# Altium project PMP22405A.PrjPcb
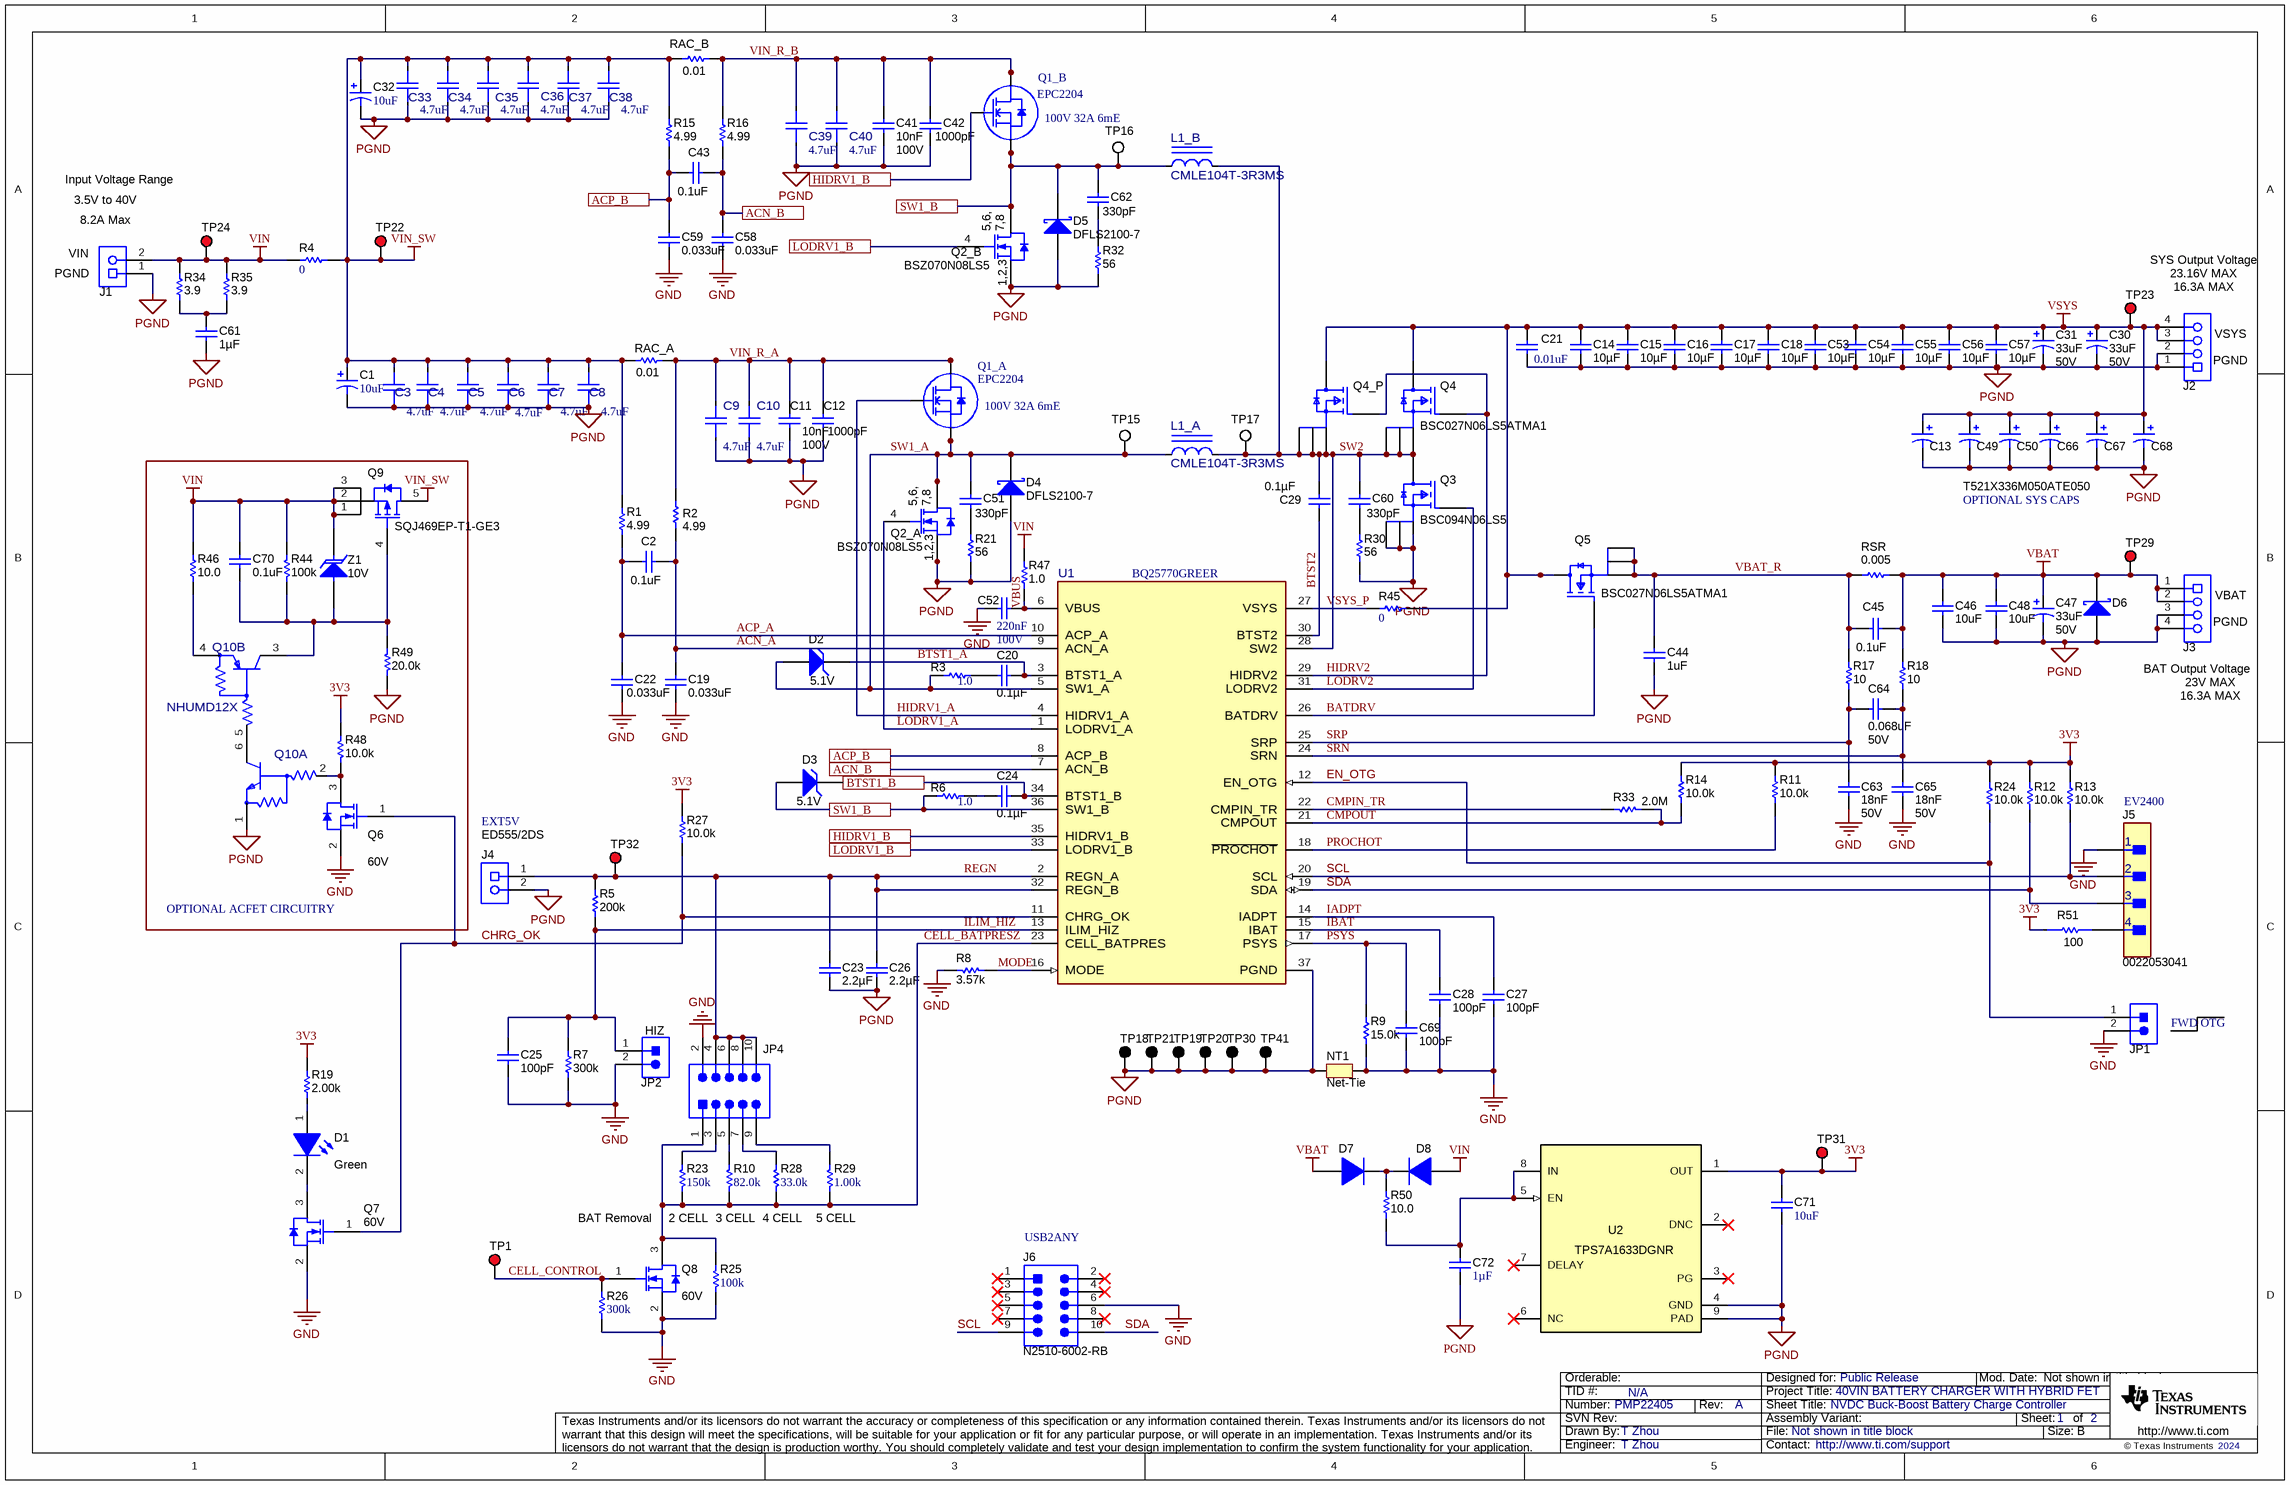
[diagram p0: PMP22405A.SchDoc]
TID: N/A; TechSupport: http://www.ti.com/support; SCH_Rev: A; PRJ_Title: 40VIN BATTERY CHARGER WITH HYBRID FET; PRJ_Number: PMP22405; PRJ_Engineer: T Zhou; PRJ_Customer: Public Release; PCB_Rev: A; PCB_Layout: T Zhou; CopyrightYear: 2024
2 sheets, 197 parts. Net scope: global (net labels, ports and power ports of the same name join across sheets).
Board file: PMP22405A.PcbDoc
Sheets:
  PMP22405A.SchDoc
  PMP22405A_Hardware.SchDoc

## Sheet PMP22405A.SchDoc: NVDC Buck-Boost Battery Charge Controller
size 431 x 279 mm; Date: Not shown in title block; ApprovedBy: Not shown in title block; CheckedBy: Not shown in title block; Author: Not shown in title block; CompanyName: Not shown in title block; DrawnBy: T Zhou; Engineer: Not shown in title block; Organization: Not shown in title block; Address1: Not shown in title block; Address2: Not shown in title block; Address3: Not shown in title block; Address4: Not shown in title block; DocumentNumber: 1; Revision: Use project parameter SCH_Rev; SheetNumber: 1; SheetTotal: 2; PageSetup: Record=PageOptions¦CenterHorizontal=True¦CenterVertical=True¦PrintScale=1.00¦XCorrection=1.00¦YCorrection=1.00¦PrintKind=0¦BorderSize=5000000¦LeftOffset=0¦BottomOffset=0¦Orientation=2¦PaperLength=1000¦PaperWidth=1000¦Scale=100¦PaperSource=15¦PrintQuality=600¦MediaType=1¦DitherType=10¦PaperKind=Letter¦PrintScaleMode=1

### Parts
C1  ValueDisplayed: 10uF  [7343-43]  (hidden comment: TR3E106K063C0600)
C2  ValueDisplayed: 0.1uF  [0603S]  (hidden comment: CGA3E2X7R1H104K080AA)
C3  ValueDisplayed: 4.7uF  [FP-C2012X5R2A475K125AC_0805-MFG]  (hidden comment: C2012X5R2A475K125AC)
C4  ValueDisplayed: 4.7uF  [FP-C2012X5R2A475K125AC_0805-MFG]  (hidden comment: C2012X5R2A475K125AC)
C5  ValueDisplayed: 4.7uF  [FP-C2012X5R2A475K125AC_0805-MFG]  (hidden comment: C2012X5R2A475K125AC)
C6  ValueDisplayed: 4.7uF  [FP-C2012X5R2A475K125AC_0805-MFG]  (hidden comment: C2012X5R2A475K125AC)
C7  ValueDisplayed: 4.7uF  [FP-C2012X5R2A475K125AC_0805-MFG]  (hidden comment: C2012X5R2A475K125AC)
C8  ValueDisplayed: 4.7uF  [FP-C2012X5R2A475K125AC_0805-MFG]  (hidden comment: C2012X5R2A475K125AC)
C9  ValueDisplayed: 4.7uF  [FP-C2012X5R2A475K125AC_0805-MFG]  (hidden comment: C2012X5R2A475K125AC)
C10  ValueDisplayed: 4.7uF  [FP-C2012X5R2A475K125AC_0805-MFG]  (hidden comment: C2012X5R2A475K125AC)
C11  Cap_F: 10nF  VDC_V: 100V  [0603S]  (hidden comment: C0603C103J1RACTU)
C12  ValueDisplayed: 1000pF  [0402S]  (hidden comment: GRM155R72A102KA01D)
C13  T521X336M050ATE050  [7343-43]  (value not drawn)
C14  ValueDisplayed: 10µF  [0805_HV]  (hidden comment: C2012JB1V106K125AC)
C15  ValueDisplayed: 10µF  [0805_HV]  (hidden comment: C2012JB1V106K125AC)
C16  ValueDisplayed: 10µF  [0805_HV]  (hidden comment: C2012JB1V106K125AC)
C17  ValueDisplayed: 10µF  [0805_HV]  (hidden comment: C2012JB1V106K125AC)
C18  ValueDisplayed: 10µF  [0805_HV]  (hidden comment: C2012JB1V106K125AC)
C19  ValueDisplayed: 0.033uF  [0603S]  (hidden comment: CGA3E3X7S2A333K080AB)
C20  ValueDisplayed: 0.1µF  [0402S]  (hidden comment: CGA2B3X7R1E104K050BB)
C21  ValueDisplayed: 0.01uF  [0603S]  (hidden comment: C0603C103J1RACTU)
C22  ValueDisplayed: 0.033uF  [0603S]  (hidden comment: CGA3E3X7S2A333K080AB)
C23  ValueDisplayed: 2.2µF  [0402S]  (hidden comment: GRM155R61E225ME15D)
C24  ValueDisplayed: 0.1µF  [0402S]  (hidden comment: CGA2B3X7R1E104K050BB)
C25  ValueDisplayed: 100pF  [0402S]  (hidden comment: GRM1555C1H101JA01D)
C26  ValueDisplayed: 2.2µF  [0402S]  (hidden comment: GRM155R61E225ME15D)
C27  ValueDisplayed: 100pF  [0402S]  (hidden comment: GRM1555C1H101JA01D)
C28  ValueDisplayed: 100pF  [0402S]  (hidden comment: GRM1555C1H101JA01D)
C29  ValueDisplayed: 0.1µF  [0402S]  (hidden comment: CGA2B3X7R1E104K050BB)
C30  ValueDisplayed: 33uF  VDC_V: 50V  [7343-43]  (hidden comment: T521X336M050ATE050)
C31  ValueDisplayed: 33uF  VDC_V: 50V  [7343-43]  (hidden comment: T521X336M050ATE050)
C32  ValueDisplayed: 10uF  [7343-43]  (hidden comment: TR3E106K063C0600)
C33  ValueDisplayed: 4.7uF  [FP-C2012X5R2A475K125AC_0805-MFG]  (hidden comment: C2012X5R2A475K125AC)
C34  ValueDisplayed: 4.7uF  [FP-C2012X5R2A475K125AC_0805-MFG]  (hidden comment: C2012X5R2A475K125AC)
C35  ValueDisplayed: 4.7uF  [FP-C2012X5R2A475K125AC_0805-MFG]  (hidden comment: C2012X5R2A475K125AC)
C36  ValueDisplayed: 4.7uF  [FP-C2012X5R2A475K125AC_0805-MFG]  (hidden comment: C2012X5R2A475K125AC)
C37  ValueDisplayed: 4.7uF  [FP-C2012X5R2A475K125AC_0805-MFG]  (hidden comment: C2012X5R2A475K125AC)
C38  ValueDisplayed: 4.7uF  [FP-C2012X5R2A475K125AC_0805-MFG]  (hidden comment: C2012X5R2A475K125AC)
C39  ValueDisplayed: 4.7uF  [FP-C2012X5R2A475K125AC_0805-MFG]  (hidden comment: C2012X5R2A475K125AC)
C40  ValueDisplayed: 4.7uF  [FP-C2012X5R2A475K125AC_0805-MFG]  (hidden comment: C2012X5R2A475K125AC)
C41  Cap_F: 10nF  VDC_V: 100V  [0603S]  (hidden comment: C0603C103J1RACTU)
C42  ValueDisplayed: 1000pF  [0402S]  (hidden comment: GRM155R72A102KA01D)
C43  ValueDisplayed: 0.1uF  [0603S]  (hidden comment: CGA3E2X7R1H104K080AA)
C44  ValueDisplayed: 1uF  [0603S]  (hidden comment: C1608X5R1H105K080AB)
C45  ValueDisplayed: 0.1uF  [0603S]  (hidden comment: CGA3E2X7R1H104K080AA)
C46  ValueDisplayed: 10uF  [1206_180]  (hidden comment: C3216X7R1V106K160AC)
C47  ValueDisplayed: 33uF  VDC_V: 50V  [7343-43]  (hidden comment: T521X336M050ATE050)
C48  ValueDisplayed: 10uF  [1206_180]  (hidden comment: C3216X7R1V106K160AC)
C49  T521X336M050ATE050  [7343-43]  (value not drawn)
C50  T521X336M050ATE050  [7343-43]  (value not drawn)
C51  ValueDisplayed: 330pF  [0603S]  (hidden comment: Capacitor)
C52  Cap_F: 220nF  VDC_V: 100V  [0603S]  (hidden comment: HMK107C7224MAHTE)
C53  ValueDisplayed: 10µF  [0805_HV]  (hidden comment: C2012JB1V106K125AC)
C54  ValueDisplayed: 10µF  [0805_HV]  (hidden comment: C2012JB1V106K125AC)
C55  ValueDisplayed: 10µF  [0805_HV]  (hidden comment: C2012JB1V106K125AC)
C56  ValueDisplayed: 10µF  [0805_HV]  (hidden comment: C2012JB1V106K125AC)
C57  ValueDisplayed: 10µF  [0805_HV]  (hidden comment: C2012JB1V106K125AC)
C58  ValueDisplayed: 0.033uF  [0603S]  (hidden comment: CGA3E3X7S2A333K080AB)
C59  ValueDisplayed: 0.033uF  [0603S]  (hidden comment: CGA3E3X7S2A333K080AB)
C60  ValueDisplayed: 330pF  [0603S]  (hidden comment: Capacitor)
C61  ValueDisplayed: 1µF  [0805_HV]  (hidden comment: C2012X7S2A105K125AE)
C62  ValueDisplayed: 330pF  [0603S]  (hidden comment: Capacitor)
C63  Cap_F: 18nF  VDC_V: 50V  [0402S]  (hidden comment: GRM155R71H183KA12D)
C64  ValueDisplayed: 0.068uF  VDC_V: 50V  [0402S]  (hidden comment: CGA2B3X7R1H683K050BB)
C65  Cap_F: 18nF  VDC_V: 50V  [0402S]  (hidden comment: GRM155R71H183KA12D)
C66  T521X336M050ATE050  [7343-43]
C67  T521X336M050ATE050  [7343-43]  (value not drawn)
C68  T521X336M050ATE050  [7343-43]  (value not drawn)
C69  ValueDisplayed: 100pF  [0402S]  (hidden comment: GRM1555C1H101JA01D)
C70  ValueDisplayed: 0.1uF  [0603S]  (hidden comment: CGA3E2X7R1H104K080AA)
C71  ValueDisplayed: 10uF  [0603S]  (hidden comment: GRM188R6YA106MA73D)
C72  ValueDisplayed: 1µF  [0805_HV]  (hidden comment: C2012X7S2A105K125AE)
D1  value Green  [LED_LTST-C190]  (hidden comment: LED)
D2  value 5.1V  [SOD-323F]  (hidden comment: D3Z5V1BF-7)
D3  value 5.1V  [SOD-323F]  (hidden comment: D3Z5V1BF-7)
D4  DFLS2100-7  [PowerDI123]
D5  DFLS2100-7  [PowerDI123]
D6  B240A-13-F  [SMA]  (value not drawn)
D7  1N4148WQ-7-F  [SOD-123]  (value not drawn)
D8  1N4148WQ-7-F  [SOD-123]  (value not drawn)
J1  Receptacle_2x1  [On-Shore_ED120_2DS]  (value not drawn)
J2  ED120/4DS  [On-Shore_ED120_4DS]  (value not drawn)
J3  ED120/4DS  [On-Shore_ED120_4DS]  (value not drawn)
J4  ED555/2DS  [TERM_BLK_ED555-2DS]
J5  0022053041  [FP-22-05-3041_HDR4-MFG]
J6  N2510-6002-RB  [CONN_2510-6002]
JP1  TSW-102-07-G-S  [TSW-102-07-G-S]  (value not drawn)
JP2  TSW-102-07-G-S  [TSW-102-07-G-S]  (value not drawn)
JP4  TSW-105-07-G-D  [TSW-105-07-G-D]  (value not drawn)
L1_A  CMLE104T-3R3MS  [FP-CMLE105T-3R3MS-99_SMT_IND_10MM85_10MM0-MFG]
L1_B  CMLE104T-3R3MS  [FP-CMLE105T-3R3MS-99_SMT_IND_10MM85_10MM0-MFG]
NT1  Net-Tie  [Net-Tie_10milWide_30milLong]  (net tie, no BOM)
Q1_A  (no value)  [D0133CT44M]
Q1_B  (no value)  [D0133CT44M]
Q2_A  BSZ070N08LS5  [PG-TSDSON-8FL]
Q2_B  BSZ070N08LS5  [PG-TSDSON-8FL]
Q3  BSC094N06LS5  [FP-BSC027N06LS5ATMA1_TDSON8-MFG]
Q4  BSC027N06LS5ATMA1  [FP-BSC027N06LS5ATMA1_TDSON8-MFG]
Q4_P  BSC027N06LS5ATMA1  [FP-BSC027N06LS5ATMA1_TDSON8-MFG]  (value not drawn)
Q5  BSC027N06LS5ATMA1  [FP-BSC027N06LS5ATMA1_TDSON8-MFG]
Q6  value 60V  [SOT-23L]  (hidden comment: MOSFET_N_D3G1S2)
Q7  value 60V  [SOT-23L]  (hidden comment: MOSFET_N_D3G1S2)
Q8  value 60V  [SOT-23L]  (hidden comment: MOSFET_N_D3G1S2)
Q9  SQJ469EP-T1-GE3  [PowerPAK_SO-8L]
Q10  NHUMD12X  [FP-NHUMD12X_TSSOP6-MFG]  (value not drawn)  (parts A,B of 2)
R1  ValueDisplayed: 4.99  [0603S]  (hidden comment: Resistor)
R2  ValueDisplayed: 4.99  [0603S]  (hidden comment: Resistor)
R3  value 1.0  [0402S]  (hidden comment: CRCW04021R00JNED)
R4  ValueDisplayed: 0  [5106]  (hidden comment: 5106)
R5  ValueDisplayed: 200k  [0402S]  (hidden comment: CRCW0402200KFKED)
R6  value 1.0  [0402S]  (hidden comment: CRCW04021R00JNED)
R7  ValueDisplayed: 300k  [0402S]  (hidden comment: CRCW0402300KFKED)
R8  ValueDisplayed: 3.57k  [0402S]  (hidden comment: CRCW04023K57FKED)
R9  value 15.0k  [0402S]  (hidden comment: CRCW040215K0FKED)
R10  ValueDisplayed: 82.0k  [0402S]  (hidden comment: RC0402FR-0782KL)
R11  value 10.0k  [0402S]  (hidden comment: CRCW040210K0FKED)
R12  value 10.0k  [0402S]  (hidden comment: CRCW040210K0FKED)
R13  value 10.0k  [0402S]  (hidden comment: CRCW040210K0FKED)
R14  value 10.0k  [0402S]  (hidden comment: CRCW040210K0FKED)
R15  ValueDisplayed: 4.99  [0603S]  (hidden comment: Resistor)
R16  ValueDisplayed: 4.99  [0603S]  (hidden comment: Resistor)
R17  ValueDisplayed: 10  [0603S]  (hidden comment: Resistor)
R18  ValueDisplayed: 10  [0603S]  (hidden comment: Resistor)
R19  value 2.00k  [0603S]  (hidden comment: Resistor)
R21  ValueDisplayed: 56  [0603S]  (hidden comment: Resistor)
R23  ValueDisplayed: 150k  [0402S]  (hidden comment: CRCW0402150KFKED)
R24  value 10.0k  [0402S]  (hidden comment: CRCW040210K0FKED)
R25  ValueDisplayed: 100k  [0402S]  (hidden comment: RC0402FR-07100KL)
R26  ValueDisplayed: 300k  [0402S]  (hidden comment: CRCW0402300KFKED)
R27  ValueDisplayed: 10.0k  [0402S]  (hidden comment: Resistor)
R28  ValueDisplayed: 33.0k  [0402S]  (hidden comment: RC0402FR-0733KL)
R29  ValueDisplayed: 1.00k  [0402S]  (hidden comment: CRCW04021K00FKED)
R30  ValueDisplayed: 56  [0603S]  (hidden comment: Resistor)
R32  ValueDisplayed: 56  [0603S]  (hidden comment: Resistor)
R33  ValueDisplayed: 2.0M  [0402S]  (hidden comment: CRCW04022M00JNED)
R34  value 3.9  [1206]  (hidden comment: Resistor)
R35  value 3.9  [1206]  (hidden comment: Resistor)
R44  ValueDisplayed: 100k  [0603S]  (hidden comment: RC0603FR-07100KL)
R45  value 0  [0402S]  (hidden comment: CRCW04020000Z0ED)
R46  ValueDisplayed: 10.0  [1206]  (hidden comment: ERJ-8ENF10R0V)
R47  ValueDisplayed: 1.0  [0603S]  (hidden comment: CRCW06031R00JNEA)
R48  ValueDisplayed: 10.0k  [0402S]  (hidden comment: CRCW040210K0FKED)
R49  ValueDisplayed: 20.0k  [0805_HV]  (hidden comment: CRCW080520K0FKEA)
R50  ValueDisplayed: 10.0  [1206]  (hidden comment: ERJ-8ENF10R0V)
R51  value 100  [FP-RC0402JR-13100RL_0402-MFG]  (hidden comment: RC0402JR-13100RL)
RAC_A  ValueDisplayed: 0.01  [1206]  (hidden comment: WSLP1206R0100FEA)
RAC_B  ValueDisplayed: 0.01  [1206]  (hidden comment: WSLP1206R0100FEA)
RSR  ValueDisplayed: 0.005  [2010]  (hidden comment: CSNL2010FT5L00)
TP1  5010  [Keystone5010]  (value not drawn)
TP15  5015  [Testpoint_Keystone_Miniature]  (value not drawn)
TP16  5015  [Testpoint_Keystone_Miniature]  (value not drawn)
TP17  5015  [Testpoint_Keystone_Miniature]  (value not drawn)
TP18  5011  [Keystone5011]  (value not drawn)
TP19  5011  [Keystone5011]  (value not drawn)
TP20  5011  [Keystone5011]  (value not drawn)
TP21  5011  [Keystone5011]  (value not drawn)
TP22  5010  [Keystone5010]  (value not drawn)
TP23  5010  [Keystone5010]  (value not drawn)
TP24  5010  [Keystone5010]  (value not drawn)
TP29  5010  [Keystone5010]  (value not drawn)
TP30  5011  [Keystone5011]  (value not drawn)
TP31  5010  [Keystone5010]  (value not drawn)
TP32  5010  [Keystone5010]  (value not drawn)
TP41  5011  [Keystone5011]  (value not drawn)
U1  BQ25770GREER  [REE0036A-MFG]
U2  TPS7A1633DGNR  [DGN0008C_N]
Z1  value 10V  [SMA]  (hidden comment: SMAJ10A)

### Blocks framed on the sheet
OPTIONAL ACFET CIRCUITRY: C70 Q6 Q9 Q10 R44 R46 R48 R49 Z1

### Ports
ACN_B, ACP_B, BTST1_B, HIDRV1_B, LODRV1_B, SW1_B

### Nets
3V3: C71.2 R11.1 R12.2 R13.2 R14.2 R19.2 R24.2 R27.1 R48.2 R51.1 TP31.1 U2.1(OUT)
GND: C19.2 C22.2 C25.2 C27.2 C28.2 C52.2 C58.2 C59.2 C63.2 C65.2 C69.2 J5.1 J6.6 JP1.2 JP2.2 JP4.2 NT1.1 Q6.2(S) Q7.2(S) Q8.2(S) R7.2 R8.1 R9.2 R25.1 R26.1
PGND: C1.2(-) C3.1 C4.1 C5.1 C6.1 C7.1 C8.1 C9.1 C10.1 C11.2 C12.2 C13.2(-) C14.2 C15.2 C16.2 C17.2 C18.2 C21.2 C23.2 C26.1 C30.2(-) C31.2(-) C32.2(-) C33.1 C34.1 C35.1 C36.1 C37.1 C38.1 C39.1 C40.1 C41.2 C42.2 C44.2 C46.2 C47.2(-) C48.2 C49.2(-) C50.2(-) C53.2 C54.2 C55.2 C56.2 C57.2 C61.2 C66.2(-) C67.2(-) C68.2(-) C71.1 C72.1 D4.2(A) D5.2(A) D6.2(A) J1.1 J2.1 J2.2 J3.3 J3.4 J4.2 NT1.2 Q2_A.1(S) Q2_A.2(S) Q2_A.3(S) Q2_B.1(S) Q2_B.2(S) Q2_B.3(S) Q3.1(S) Q3.2(S) Q3.3(S) Q10.1(GND1) R21.1 R30.1 R32.1 R49.1 TP18.1 TP19.1 TP20.1 TP21.1 TP30.1 TP41.1 U1.37(PGND) U2.4(GND) U2.9(PAD)
VBAT: C45.2 C46.1 C47.1(+) C48.1 D6.1(K) D7.2(A) J3.1 J3.2 R18.2 RSR.2 TP29.1
VIN: C70.2 D8.2(A) J1.2 Q9.1(S) Q9.2(S) Q9.3(S) R4.1 R34.2 R35.2 R44.2 R46.2 R47.2 TP24.1 Z1.1(K)
VIN_SW: C1.1(+) C3.2 C4.2 C5.2 C6.2 C7.2 C8.2 C32.1(+) C33.2 C34.2 C35.2 C36.2 C37.2 C38.2 Q9.5(D) R1.2 R4.2 R15.2 RAC_A.1 RAC_B.1 TP22.1
VSYS: C13.1(+) C14.1 C15.1 C16.1 C17.1 C18.1 C21.1 C30.1(+) C31.1(+) C49.1(+) C50.1(+) C53.1 C54.1 C55.1 C56.1 C57.1 C66.1(+) C67.1(+) C68.1(+) J2.3 J2.4 Q4.5-6-7-8(D) Q4_P.5-6-7-8(D) Q5.5-6-7-8(D) R45.2 TP23.1
ACN_A: C2.2 C19.1 R2.1 U1.9(ACN_A)
ACN_B: C43.2 C58.1 R16.1 U1.7(ACN_B) ; port ACN_B
ACP_A: C2.1 C22.1 R1.1 U1.10(ACP_A)
ACP_B: C43.1 C59.1 R15.1 U1.8(ACP_B) ; port ACP_B
BATDRV: Q5.4(G) U1.26(BATDRV)
BTST1_A: C20.1 D2.1(K) U1.3(BTST1_A)
BTST1_B: C24.1 D3.1(K) U1.34(BTST1_B) ; port BTST1_B
BTST2: C29.1 U1.30(BTST2)
CELL_BATPRESZ: JP4.1 Q8.3(D) R10.1 R23.1 R25.2 R28.1 R29.1 U1.23(CELL_BATPRES)
CELL_CONTROL: Q8.1(G) R26.2 TP1.1
CHRG_OK: Q6.1(G) Q7.1(G) R27.2 U1.11(CHRG_OK)
CMPIN_TR: R33.2 U1.22(CMPIN_TR)
CMPOUT: R14.1 R33.1 U1.21(CMPOUT)
EN_OTG: JP1.1 R24.1 U1.12(EN_OTG)
HIDRV1_A: Q1_A.1(G) U1.4(HIDRV1_A)
HIDRV1_B: Q1_B.1(G) U1.35(HIDRV1_B) ; port HIDRV1_B
HIDRV2: Q4.4(G) Q4_P.4(G) U1.29(HIDRV2)
IADPT: C27.1 U1.14(IADPT)
IBAT: C28.1 U1.15(IBAT)
ILIM_HIZ: C25.1 JP2.1 R5.2 R7.1 U1.13(ILIM_HIZ)
LODRV1_A: Q2_A.4(G) U1.1(LODRV1_A)
LODRV1_B: Q2_B.4(G) U1.33(LODRV1_B) ; port LODRV1_B
LODRV2: Q3.4(G) U1.31(LODRV2)
MODE: R8.2 U1.16(MODE)
PROCHOT: R11.2 U1.18(~{PROCHOT})
PSYS: C69.1 R9.1 U1.17(PSYS)
REGN: C23.1 C26.2 J4.1 JP4.4 JP4.6 JP4.8 JP4.10 R5.1 TP32.1 U1.2(REGN_A) U1.32(REGN_B)
SCL: J5.2 J6.9 R13.1 U1.20(SCL)
SDA: J5.3 J6.10 R12.1 U1.19(SDA)
SRN: C64.2 C65.1 R18.1 U1.24(SRN)
SRP: C63.1 C64.1 R17.1 U1.25(SRP)
SW1_A: C51.1 D2.2(A) D4.1(K) L1_A.1 Q1_A.2(S) Q1_A.4(S) Q1_A.6(S) Q2_A.5(D) Q2_A.6(D) Q2_A.7(D) Q2_A.8(D) Q2_A.9(D) R3.1 TP15.1 U1.5(SW1_A)
SW1_B: C62.1 D3.2(A) D5.1(K) L1_B.1 Q1_B.2(S) Q1_B.4(S) Q1_B.6(S) Q2_B.5(D) Q2_B.6(D) Q2_B.7(D) Q2_B.8(D) Q2_B.9(D) R6.1 TP16.1 U1.36(SW1_B) ; port SW1_B
SW2: C29.2 C60.1 L1_A.2 L1_B.2 Q3.5-6-7-8(D) Q4.1(S) Q4.2(S) Q4.3(S) Q4_P.1(S) Q4_P.2(S) Q4_P.3(S) TP17.1 U1.28(SW2)
VBAT_R: C44.1 C45.1 Q5.1(S) Q5.2(S) Q5.3(S) R17.2 RSR.1
VBUS: C52.1 R47.1 U1.6(VBUS)
VIN_R_A: C9.2 C10.2 C11.1 C12.1 Q1_A.3(D) Q1_A.5(D) R2.2 RAC_A.2
VIN_R_B: C39.2 C40.2 C41.1 C42.1 Q1_B.3(D) Q1_B.5(D) R16.2 RAC_B.2
VSYS_P: R45.1 U1.27(VSYS)
NetC20_2: C20.2 R3.2
NetC24_2: C24.2 R6.2
NetC51_2: C51.2 R21.2
NetC60_2: C60.2 R30.2
NetC61_1: C61.1 R34.1 R35.1
NetC62_2: C62.2 R32.2
NetC70_1: C70.1 Q9.4(G) Q10.3(O2) R44.1 R49.2 Z1.2(A)
NetC72_2: C72.2 R50.1 U2.5(EN) U2.8(IN)
NetD1_1: D1.1(A) R19.1
NetD1_2: D1.2(K) Q7.3(D)
NetD7_1: D7.1(K) D8.1(K) R50.2
NetJ5_4: J5.4 R51.2
NetJP4_3: JP4.3 R23.2
NetJP4_5: JP4.5 R10.2
NetJP4_7: JP4.7 R28.2
NetJP4_9: JP4.9 R29.2
NetQ6_3: Q6.3(D) Q10.2(I1) R48.1
NetQ10_4: Q10.4(GND2) R46.1
NetQ10_5: Q10.5(I2) Q10.6(O1)

Not connected (* = marked no-connect by the designer): J6 1* 2* 3* 4* 5* 7* 8*; U2 2(DNC)* 3(PG)* 6(NC)* 7(DELAY)*

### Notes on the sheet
- 3.5V to 40V
- (near J1) 8.2A Max
- Input Voltage Range
- (near J1) PGND
- (near J1) VIN
- SYS Output Voltage
- 23.16V MAX
- 16.3A MAX
- (near J2) VSYS
- (near J2) PGND
- OPTIONAL SYS CAPS
- (near J3) PGND
- (near J3) VBAT
- (near J3) BAT Output Voltage
- (near J3) 23V MAX
- (near J4) EXT5V
- EV2400
- (near JP2) HIZ
- (near JP1) FWD OTG
- BAT Removal
- 2 CELL
- 3 CELL
- (near R28) 4 CELL
- (near R29) 5 CELL
- (near J6) USB2ANY

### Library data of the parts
C1 C32 = CMP-0011990-2: CAP, TA, 10 uF, 63 V, +/- 10%, 0.6 ohm, SMD; Manufacturer: Vishay-Sprague; Polarized: Y; CompType: Capacitor; Value: 10uF; Cap_F: 10µF; Value1: 0.6 ohm; VDC_V: 63V; ESR_ohm: 0.6; IRMS_A: 740mA; TaMin_C: -55°C; TaMax_C: 125°C; AEC Category: Q200; SizeAreaWB_mm2: 58.59; SizeArea_mm2: 31.39; SizeX_mm: 7.3; SizeY_mm: 4.3; U/M: EA
C2 C43 = CMP-0007078-4: CAP, CERM, 0.1 uF, 50 V, +/- 10%, X7R, AEC-Q200 Grade 1, 0603; Manufacturer: TDK; Polarized: N; Value: 0.1uF; U/M: EA; Cap_F: 100nF; ESR_ohm: 29.6m; Value1: 0.0296 ohm; VDC_V: 50V; IRMS_A: 971.99mA; TaMin_C: -55°C; TaMax_C: 125°C; Cap_Case: 0603; AEC Category: Q200; AEC Qualified: Y; AEC Grade: 1; SizeAreaWB_mm2: 4.68; SizeX_mm: 1.6; SizeY_mm: 0.8; SizeArea_mm2: 1.28
C3-C10 C33-C40 = CMP-0098058-1: 4.7 µF ±10% 100V Ceramic Capacitor X5R 0805 (2012 Metric); Manufacturer: TDK; Value: 4.7µF; TempCo: 15%; SizeZ_mm: 1.5mm; AEC Qualified: No
C11 C41 = CMP-0006848-4: CAP, CERM, 0.01 uF, 100 V, +/- 5%, X7R, 0603; Manufacturer: Kemet; Polarized: N; Value: 0.01uF; U/M: EA; Value1: Unknown; TaMin_C: -55°C; TaMax_C: 125°C; Cap_Case: 0603; AEC Category: Q200; SizeAreaWB_mm2: 4.68; SizeZ_mm: 1; SizeX_mm: 1.6; SizeY_mm: 0.8; SizeArea_mm2: 1.28
C12 C42 = CMP-0006699-2: CAP, CERM, 1000 pF, 100 V, +/- 10%, X7R, 0402; Manufacturer: MuRata; Polarized: N; Value: 1000pF; U/M: EA; Cap_F: 1nF; Value1: Unknown; VDC_V: 100V; TaMin_C: -55°C; TaMax_C: 125°C; Cap_Case: 0402; AEC Category: Q200; SizeArea_mm2: 0.5; SizeAreaWB_mm2: 3; SizeX_mm: 1; SizeZ_mm: 0.6
C13 C49 C50 C66-C68 = CMP-0012653-3: CAP, Tantalum Polymer, 33 uF, 50 V, +/- 20%, 0.05 ohm, 7343-43 SMD; Manufacturer: Kemet; AEC Category: Q200; AEC Qualified: N; Cap_Case: 7.3x4.3x4.3mm; Cap_F: 33µF; CompType: Capacitor; ESR_ohm: 50m; IRMS_A: 2.2A; Polarized: Y; SizeArea_mm2: 31.39; SizeAreaWB_mm2: 58.59; SizeX_mm: 7.3; SizeY_mm: 4.3; TaMax_C: 125°C; TaMin_C: -55°C; Value2: 50V; Value: 33uF
C14-C18 C53-C57 = CMP-0085894-1: CAP, CERM, 10 µF, 50 V,+/- 10%, JB, 0805; PartNumber: GRM21BR61H106KE43L; Manufacturer: muRata; Polarized: N; Value: 10uF; U/M: EA; VDC_V: 50V; TaMin_C: -25°C; TaMax_C: 85°C; Cap_Case: 0805; SizeArea_mm2: 2.5; SizeAreaWB_mm2: 6.75; SizeX_mm: 2; SizeY_mm: 1.25; SizeZ_mm: 1.45; AEC Category: Q200
C19 C22 C58 C59 = CMP-0007100-4: CAP, CERM, 0.033 uF, 100 V, +/- 10%, X7S, AEC-Q200 Grade 1, 0603; Manufacturer: TDK; Polarized: N; U/M: EA; Cap_F: 33nF; ESR_ohm: 0.1396; Value1: 0.139637 ohm; VDC_V: 100V; IRMS_A: 462.257mA; TaMin_C: -55°C; TaMax_C: 125°C; Cap_Case: 0603; AEC Category: Q200; AEC Qualified: Y; AEC Grade: 1; SizeArea_mm2: 1.28; SizeAreaWB_mm2: 4.68; SizeX_mm: 1.6; SizeY_mm: 0.8
C20 C24 C29 = CMP-0080610-1: CAP, CERM, 0.1 µF, 25 V,+/- 10%, X7R, AEC-Q200 Grade 1, 0402; Manufacturer: TDK; Polarized: N; Value: 0.1uF; U/M: EA; Cap_F: 100nF; VDC_V: 25V; TaMin_C: -55°C; TaMax_C: 125°C; Cap_Case: 0402; SizeAreaWB_mm2: 3; SizeZ_mm: 0.6; SizeX_mm: 1; SizeY_mm: 0.5; AEC Qualified: Y; AEC Category: Q200
C21 = CMP-0006848-4: CAP, CERM, 0.01 uF, 100 V, +/- 5%, X7R, 0603; Manufacturer: Kemet; Polarized: N; Value: 0.01uF; U/M: EA; Cap_F: 10nF; Value1: Unknown; VDC_V: 100V; TaMin_C: -55°C; TaMax_C: 125°C; Cap_Case: 0603; SizeAreaWB_mm2: 4.68; SizeZ_mm: 1; SizeX_mm: 1.6; SizeY_mm: 0.8; SizeArea_mm2: 1.28; AEC Category: Q200
C23 C26 = CMP-0081010-1: CAP, CERM, 2.2 µF, 25 V,+/- 20%, X5R, 0402; Manufacturer: MuRata; Polarized: N; Value: 2.2uF; U/M: EA; VDC_V: 25V; TaMin_C: -55°C; TaMax_C: 85°C; Cap_Case: 0402; SizeAreaWB_mm2: 3; SizeZ_mm: 0.6; SizeX_mm: 1; SizeY_mm: 0.5; AEC Category: Q200
C25 C27 C28 C69 = CMP-0006410-2: CAP, CERM, 100 pF, 50 V, +/- 5%, C0G/NP0, 0402; Manufacturer: MuRata; Polarized: N; Value: 100pF; U/M: EA; Value1: Unknown; VDC_V: 50V; TaMin_C: -55°C; TaMax_C: 125°C; Cap_Case: 0402; SizeAreaWB_mm2: 3; SizeZ_mm: 0.6; SizeX_mm: 1; SizeY_mm: 0.5; AEC Category: Q200
C30 C31 C47 = CMP-0012653-3: CAP, Tantalum Polymer, 33 uF, 50 V, +/- 20%, 0.05 ohm, 7343-43 SMD; Manufacturer: Kemet; Polarized: Y; CompType: Capacitor; Value: 33uF; Cap_F: 33µF; ESR_ohm: 50m; IRMS_A: 2.2A; TaMin_C: -55°C; TaMax_C: 125°C; Cap_Case: 7.3x4.3x4.3mm; AEC Category: Q200; AEC Qualified: N; SizeAreaWB_mm2: 58.59; SizeArea_mm2: 31.39; SizeX_mm: 7.3; SizeY_mm: 4.3
C44 = CMP-0007011-5: CAP, CERM, 1 uF, 50 V, +/- 10%, X5R, 0603; Manufacturer: TDK; Polarized: N; Value: 1uF; U/M: EA; Cap_F: 1µF; ESR_ohm: 5.522m; Value1: 0.005522 ohm; VDC_V: 50V; IRMS_A: 2.2162A; TaMin_C: -55°C; TaMax_C: 85°C; Cap_Case: 0603; SizeAreaWB_mm2: 4.68; SizeZ_mm: 1; SizeX_mm: 1.6; SizeY_mm: 0.8; SizeArea_mm2: 1.28; AEC Category: Q200
C45 C70 = CMP-0007078-4: CAP, CERM, 0.1 uF, 50 V, +/- 10%, X7R, AEC-Q200 Grade 1, 0603; Manufacturer: TDK; Polarized: N; Value: 0.1uF; U/M: EA; Cap_F: 100nF; ESR_ohm: 29.6m; Value1: 0.0296 ohm; VDC_V: 50V; IRMS_A: 971.99mA; TaMin_C: -55°C; TaMax_C: 125°C; Cap_Case: 0603; SizeAreaWB_mm2: 4.68; SizeZ_mm: 1; SizeX_mm: 1.6; SizeY_mm: 0.8; SizeArea_mm2: 1.28; AEC Qualified: Y; AEC Category: Q200
C46 C48 = CMP-0008705-2: CAP, CERM, 10 uF, 35 V, +/- 10%, X7R, 1206; Manufacturer: TDK; Polarized: N; Value: 10uF; U/M: EA; Cap_F: 10µF; ESR_ohm: 2.229m; Value1: 0.002229 ohm; VDC_V: 35V; IRMS_A: 4.8593A; TaMin_C: -55°C; TaMax_C: 125°C; SizeArea_mm2: 5.12; SizeAreaWB_mm2: 10.92; SizeX_mm: 3.2; SizeY_mm: 1.6; SizeZ_mm: 1.8; AEC Category: Q200
C51 C60 C62 = CMP-0007449-4: CAP, CERM, 330 pF, 50 V, +/- 10%, X7R, 0603; PartNumber: GRM188R71H331KA01D; Manufacturer: MuRata; Polarized: N; Value: 330pF; U/M: EA; Value1: Unknown; VDC_V: 50V; TaMin_C: -55°C; TaMax_C: 125°C; Cap_Case: 0603; SizeAreaWB_mm2: 4.68; SizeZ_mm: 1; SizeX_mm: 1.6; SizeY_mm: 0.8; SizeArea_mm2: 1.28; AEC Category: Q200
C52 = CMP-0077895-3: CAP, CERM, 0.22 µF, 100 V,+/- 20%, X7S, AEC-Q200 Grade 1, 0603; Manufacturer: Taiyo Yuden; Polarized: N; Value: 0.22uF; ValueDisplayed: 0.22µF; U/M: EA; TaMin_C: -55°C; TaMax_C: 125°C; Cap_Case: 0603; AEC Category: Q200; AEC Qualified: Y; AEC Grade: 1; SizeAreaWB_mm2: 4.68; SizeZ_mm: 1.0; SizeX_mm: 1.6; SizeY_mm: 0.8; SizeArea_mm2: 1.28
C61 = CMP-0750059-1: CAP, CERM, 1 µF, 100 V,+/- 10%, X7S, 0805; Manufacturer: TDK; Polarized: N; Value: 1uF; U/M: EA; VDC_V: 100V; TaMin_C: -55°C; TaMax_C: 125°C; Cap_Case: 0805; SizeAreaWB_mm2: 6.75; SizeZ_mm: 1.45; SizeX_mm: 2; SizeY_mm: 1.25; SizeArea_mm2: 2.5; AEC Category: Q200; Green_REACh: Incomplete; Green_Lifecycle: Active
C63 C65 = CMP-0006681-2: CAP, CERM, 0.018 uF, 50 V, +/- 10%, X7R, 0402; Manufacturer: MuRata; Polarized: N; U/M: EA; Value1: Unknown; TaMin_C: -55°C; TaMax_C: 125°C; Cap_Case: 0402; AEC Category: Q200; SizeArea_mm2: 0.5; SizeAreaWB_mm2: 3; SizeX_mm: 1; SizeZ_mm: 0.6
C64 = CMP-0006331-2: CAP, CERM, 0.068 uF, 50 V, +/- 10%, X7R, AEC-Q200 Grade 1, 0402; Manufacturer: TDK; Polarized: N; U/M: EA; Cap_F: 68nF; ESR_ohm: 0.05606; Value1: 0.05606 ohm; IRMS_A: 684.724mA; TaMin_C: -55°C; TaMax_C: 125°C; Cap_Case: 0402; SizeAreaWB_mm2: 3; SizeZ_mm: 0.6; SizeX_mm: 1; SizeY_mm: 0.5; AEC Qualified: Y; AEC Category: Q200
C71 = CMP-0007355-6: CAP, CERM, 10 uF, 35 V, +/- 20%, X5R, 0603; Manufacturer: Murata; Polarized: N; Value: 10uF; U/M: EA; Cap_F: 10µF; Value1: Unknown; VDC_V: 35V; TaMin_C: -55°C; TaMax_C: 85°C; Cap_Case: 0603; SizeAreaWB_mm2: 4.68; SizeZ_mm: 1; SizeX_mm: 1.6; SizeY_mm: 0.8; SizeArea_mm2: 1.28; AEC Category: Q200
C72 = CMP-0750059-1: CAP, CERM, 1 µF, 100 V,+/- 10%, X7S, 0805; Manufacturer: TDK; VDC_V: 100V; SizeZ_mm: 1.45; AEC Qualified: N; TaMax_C: 125°C; SizeAreaWB_mm2: 6.75; SizeY_mm: 1.25; Green_REACh: Incomplete; TaMin_C: -55°C; Cap_Case: 0805; U/M: EA; SizeX_mm: 2; Green_Lifecycle: Active; SizeArea_mm2: 2.5; Value: 1uF; AEC Category: Q200
D1 = CMP-0002827-3: LED, Green, SMD; Manufacturer: Lite-On; PartNumber: LTST-C190GKT; Vf_V: 2.1V; Io_A: 20mA; Power_TotalModule: 100mW; Value1: 0.1W
D2 D3 = CMP-0005870-3: Diode, Zener, 5.1 V, 400 mW, SOD-323F; Manufacturer: Diodes Inc.; SizeAreaWB_mm2: 7.875; SizeArea_mm2: 3.125; AEC Category: Q101; SizeZ_mm: 0.8; RJA_CperW: 313; Power_W: 400mW; SizeY_mm: 1.25; Value1: 0.4W; SizeX_mm: 2.5
D4 D5 = CMP-0076948-2: Diode, Schottky, 100 V, 2 A, PowerDI123; Manufacturer: Diodes Inc.; SizeAreaWB_mm2: 13.066; SizeArea_mm2: 6.586; Vr_V: 100V; Value1: 2A; SizeX_mm: 3.7; AEC Category: Q101; SizeZ_mm: 0.98; TJmax_C: 175°C; Value2: 0.86V; Value: 100V; Green_REACh: Incomplete; SizeY_mm: 1.78; Green_Lifecycle: Not Set; Vf_V: 860mV
D6 = CMP-0028403-2: Diode, Schottky, 40 V, 2 A, SMA; Manufacturer: Diodes Inc.; Vf_V: 500mV; Value: 40V; Value1: 2A; Value2: 0.5V; TJmax_C: 150°C; RJC_CperW: 20; Green_REACh: Passed; SizeAreaWB_mm2: 37.3428; SizeZ_mm: 2.87; SizeX_mm: 5.59; SizeArea_mm2: 16.3228; SizeY_mm: 2.92; Green_Lifecycle: Active; AEC Category: Q101
D7 D8 = CMP-0750148-1: Diode, Switching, 100 V, 0.3 A, AEC-Q101, SOD-123; Manufacturer: Diodes Inc.; Value: 100V; Vf_V: 1.25V; Value1: 0.3A; Io_A: 300mA; TJmax_C: 150°C; SizeAreaWB_mm2: 13.095; SizeZ_mm: 1.35; SizeX_mm: 3.85; SizeY_mm: 1.7; SizeArea_mm2: 6.545; AEC Qualified: Y; AEC Category: Q101
J1 = CMP-0074910-1: Terminal Block, 5.08 mm, 2x1, Brass, TH; PartNumber: ED120/2DS; Manufacturer: On-Shore Technology; U/M: EA; Cert_VDE: Y; CNHeader: False; Current_A: 15A; Green_Lifecycle: Not Set; Shrouded: N; Gender: Female; Green_REACh: Incomplete; Voltage_V: 300V; Row_Count: 1; Pitch_mm: 5.08; CT: True
J2 J3 = CMP-0074939-1: Terminal Block, 5.08 mm, 4x1, Brass, TH; Manufacturer: On-Shore Technology; Cert_VDE: Y; CNHeader: False; Current_A: 15A; Green_Lifecycle: Not Set; Shrouded: N; Gender: Female; Green_REACh: Incomplete; Voltage_V: 300V; Row_Count: 1; Pitch_mm: 5.08; CT: True
J4 = CMP-0074913-1: Terminal Block, 3.5mm Pitch, 2x1, TH; Manufacturer: On-Shore Technology; Cert_VDE: Y; CNHeader: False; Current_A: 6A; Green_Lifecycle: Active; Shrouded: N; Gender: Female; Green_REACh: Passed; Voltage_V: 150V; Row_Count: 1; Pitch_mm: 3.5; ContactFinish: Brass; CT: True
J5 = CMP-0089047-2: Connector Header Through Hole, Right Angle 4 position 0.100" (2.54mm); Manufacturer: Molex; Row_Count: 1; Current_A: 4A; ContactFinish: Tin,Nickel; Voltage_V: 500V
J6 = CMP-0055448-2: Header (shrouded), 100mil, 5x2, High-Temperature, Gold, TH; Manufacturer: 3M; Green_Lifecycle: Active; Green_REACh: Passed
JP1 JP2 = CMP-0075405-3: Header, 100mil, 2x1, Gold, TH; Manufacturer: Samtec; Green_REACh: Passed; Green_Lifecycle: Active; Cert_CSA: Y; Cert_CULUS: N; Current_A: 6.3A; Gender: Male; Pitch_mm: 2.54; Row_Count: 1; Voltage_V: 550V
JP4 = CMP-0075410-2: Header, 100mil, 5x2, Gold, TH; Manufacturer: Samtec; Cert_CSA: Y; Green_Lifecycle: Active; Pitch_mm: 2.54; Shrouded: N; Row_Count: 2; Current_A: 6.3A; Voltage_V: 550V; Green_REACh: Passed; Gender: Male
L1_A L1_B = CMP-0089738-2: Fixed Inductor 4.7uH 20% 100kHz 15A 7.5mOhm; PartNumber: CMLE105T-4R7MS; Manufacturer: Cyntec; DCR_ohm: 7.5m; Isat: 22A; Standoff Height: 0mm; Material: Metal Dust; AEC Qualified: No; Ind_H: 4.7µH; SizeZ_mm: 4mm
NT1 = CMP-0078142-6: Single point connection between nets.
Q1_A Q1_B = EPC2204: 100V 32A 6mE; Manufacturer: EPC
Q2_A = CMP-0084434-1: MOSFET, N-CH, 80 V, 40 A, 8-PG-TSDSON; Manufacturer: Infineon Technologies; Alternate Manufacturer: None; SizeZ_mm: 1.1; ChType: N; Value2: 22 nC; VdsMax_V: 80V; SizeX_mm: 3.3; Vgs_V: 20V; QgTyp_nC: 22; Value: 80V; SizeArea_mm2: 10.89; AEC Category: Q101; IdsMax_A: 40A; SizeAreaWB_mm2: 18.49; Rdson45_ohm: 13.5m; Value1: 0.0135 ohm; ChMode: Enhancement
Q2_B = CMP-0084434-1: MOSFET, N-CH, 80 V, 40 A, 8-PG-TSDSON; Manufacturer: Infineon Technologies; Alternate Manufacturer: None; VdsMax_V: 80V; SizeArea_mm2: 10.89; Vgs_V: 20V; SizeX_mm: 3.3; AEC Qualified: N; IdsMax_A: 40A; Value2: 22 nC; Value1: 0.0135 ohm; ChMode: Enhancement; SizeAreaWB_mm2: 18.49; Rdson45_ohm: 13.5m; AEC Category: Q101; SizeZ_mm: 1.1; QgTyp_nC: 22; Value: 80V
Q3 = CMP-0096418-1: N-Channel 60 V 100A (Tc) 83W (Tc) Surface Mount PG-TDSON-8-7; Manufacturer: Infineon; PartNumber: BSC027N06LS5ATMA1; VdsMax_V: 1.2V; Rdson45_ohm: 2.3m; QgTyp_nC: 24nC @ 4.5V; Vgs_V: 20V; IdsMax_A: 23A; AEC Qualified: No; SizeZ_mm: 1mm; ChMode: False; Pulse Drain Current: 536A; Number Of N Channels: 1; Transconductance: 120S; Turn Off Delay Time: 25ns; Typ Forward Diode Voltage: 0.8V; Power_W: 2.5W; Threshold Vgs Min: 1.1V; Threshold Vgs Max: 2.3V; Turn On Delay Time: 7.7ns; Drain To Source Breakdown Voltage: 60V; Reverse Recovery Charge: 36nC; Reverse Recovery Time: 40ns; Input Capacitace At Vds: 3300pF @ 30V; Rthja Max: 50K/W; TJmax_C: +150°C
Q4 Q4_P Q5 = CMP-0096418-1: N-Channel 60 V 100A (Tc) 83W (Tc) Surface Mount PG-TDSON-8-7; Manufacturer: Infineon; VdsMax_V: 1.2V; Rdson45_ohm: 2.3m; QgTyp_nC: 24nC @ 4.5V; Vgs_V: 20V; IdsMax_A: 23A; AEC Qualified: No; SizeZ_mm: 1mm; ChMode: False; Pulse Drain Current: 536A; Number Of N Channels: 1; Transconductance: 120S; Turn Off Delay Time: 25ns; Typ Forward Diode Voltage: 0.8V; Power_W: 2.5W; Threshold Vgs Min: 1.1V; Threshold Vgs Max: 2.3V; Turn On Delay Time: 7.7ns; Drain To Source Breakdown Voltage: 60V; Reverse Recovery Charge: 36nC; Reverse Recovery Time: 40ns; Input Capacitace At Vds: 3300pF @ 30V; Rthja Max: 50K/W; TJmax_C: +150°C
Q6 Q8 = CMP-0000772-1: MOSFET, N-CH, 60 V, 0.26 A, SOT-23; PartNumber: 2N7002ET1G; Manufacturer: ON Semiconductor; Alternate Manufacturer: None; U/M: EA; ChType: N; Rdson45_ohm: 3; Value2: 0.81 nC; QgTyp_nC: 0.81; Vgs_V: 20V; IdsMax_A: 2.6dA; SizeZ_mm: 1.1; SizeX_mm: 2.5; SizeArea_mm2: 7.5; AEC Category: Q101; SizeAreaWB_mm2: 14
Q7 = CMP-0000772-1: MOSFET, N-CH, 60 V, 0.26 A, SOT-23; PartNumber: 2N7002ET1G; Manufacturer: ON Semiconductor; Alternate Manufacturer: None; U/M: EA; ChType: N; Rdson45_ohm: 3; Value2: 0.81 nC; QgTyp_nC: 0.81; Vgs_V: 20V; IdsMax_A: 2.6dA; AEC Category: Q101; SizeZ_mm: 1.1; SizeX_mm: 2.5; SizeArea_mm2: 7.5; SizeAreaWB_mm2: 14
Q9 = CMP-0000142-3: MOSFET, P-CH, -80 V, -32 A, AEC-Q101, PowerPAK_SO-8L; Manufacturer: Vishay-Siliconix; Alternate Manufacturer: None; QgTyp_nC: 101; Value: -80V; ChMode: Enhancement; SizeAreaWB_mm2: 58.1095; SizeZ_mm: 1.14; SizeArea_mm2: 31.5495; ChType: P; SizeY_mm: 5.13; AEC Qualified: Y; AEC Category: Q101; IdsMax_A: -32A; SizeX_mm: 6.15; Vgs_V: -20V; Value2: 101 nC
Q10 = CMP-0121666-1: Pre-Biased Bipolar Transistor (BJT) 1 NPN, 1 PNP - Pre-Biased (Dual) 80V 100mA 170MHz, 150MHz 350mW Surface Mount 6-TSSOP; Manufacturer: Nexperia; TJmax_C: +150°C; AEC Qualified: Yes; SizeZ_mm: 1.1mm; AEC Grade: Grade 0; Rthja Max: 358K/W; NPN: 1; TaMax_C: 150°C; TaMin_C: -55°C; Vcesat1_V: 100mV; Emitter Base Voltage: 10V; Hfe Min: 100; Hfe Testic: 10mA; Hfe Testvce: 5V; Number Of Elements: 2; Unity Gain Freq: 170/150MHz
R1 R2 R15 R16 = CMP-0022478-4: RES, 4.99, 1%, 0.1 W, AEC-Q200 Grade 0, 0603; PartNumber: CRCW06034R99FKEA; Manufacturer: Vishay-Dale; Value: 4.99; Value_Code: 4R99; Power_W: 100mW; Value2: 0.1W; VDC_V: 75V; TempCo: 100 ppm/C; EIA_Code: E96; U/M: EA; AEC Category: Q200; AEC Qualified: Y; AEC Grade: 0; SizeArea_mm2: 1.28; SizeX_mm: 1.6; SizeY_mm: 0.8; SizeZ_mm: 1
R3 R6 = CMP-0026866-3: RES, 1.0, 5%, 0.063 W, AEC-Q200 Grade 0, 0402; Manufacturer: Vishay-Dale; Res_ohm: 1; Value_Code: 1R00; Power_W: 63mW; Value2: 0.063W; VDC_V: 50V; TempCo: 200 ppm/C; EIA_Code: E24; SizeY_mm: 0.5; SizeZ_mm: 0.6; AEC Qualified: Y; AEC Category: Q200; AEC Grade: 0
R4 = CMP-0020833-2: RES, 0, 1%, 0.5 W, 0805; Manufacturer: Keystone; Power_W: 500mW; TempCo: ppm/C; U/M: EA; Value: 0; SizeX_mm: 2; SizeY_mm: 1.25; SizeZ_mm: 0.84; Value2: 0.5W; SizeArea_mm2: 2.5; AEC Qualified: N; AEC Category: Q200
R5 = CMP-0026158-2: RES, 200 k, 1%, 0.063 W, AEC-Q200 Grade 0, 0402; Manufacturer: Vishay-Dale; Value: 200k; Power_W: 63mW; Value2: 0.063W; VDC_V: 50V; TempCo: 100 ppm/C; EIA_Code: E96; SizeX_mm: 1; SizeY_mm: 0.5; SizeZ_mm: 0.6; AEC Qualified: Y; AEC Category: Q200; AEC Grade: 0
R7 R26 = CMP-0026279-2: RES, 300 k, 1%, 0.063 W, AEC-Q200 Grade 0, 0402; Manufacturer: Vishay-Dale; Value: 300k; Power_W: 63mW; Value2: 0.063W; VDC_V: 50V; TempCo: 100 ppm/C; SizeX_mm: 1; SizeY_mm: 0.5; SizeZ_mm: 0.6; AEC Qualified: Y; AEC Category: Q200; AEC Grade: 0
R8 = CMP-0026336-2: RES, 3.57 k, 1%, 0.063 W, AEC-Q200 Grade 0, 0402; Manufacturer: Vishay-Dale; Value: 3.57k; Value_Code: 3k57; Power_W: 63mW; Value2: 0.063W; VDC_V: 50V; TempCo: 100 ppm/C; EIA_Code: E96; SizeX_mm: 1; SizeY_mm: 0.5; SizeZ_mm: 0.6; AEC Qualified: Y; AEC Category: Q200; AEC Grade: 0
R9 = CMP-0026027-3: RES, 15.0 k, 1%, 0.063 W, AEC-Q200 Grade 0, 0402; Manufacturer: Vishay-Dale; Res_ohm: 15k; Value_Code: 15k0; Power_W: 63mW; Value2: 0.063W; VDC_V: 50V; TempCo: 100 ppm/C; EIA_Code: E96; SizeX_mm: 1; SizeY_mm: 0.5; SizeZ_mm: 0.6; AEC Qualified: Y; AEC Category: Q200; AEC Grade: 0
R10 = CMP-0026744-1: RES, 82.0 k, 1%, 0.063 W, 0402; Manufacturer: Yageo America; Value: 82.0k; Res_ohm: 82k; Value_Code: 82k0; Power_W: 63mW; Value2: 0.063W; VDC_V: 50V; TempCo: 100 ppm/C; SizeX_mm: 1; SizeY_mm: 0.5; SizeZ_mm: 0.6; AEC Qualified: N; AEC Category: Q200; U/M: EA
R11-R14 R24 = CMP-0025958-3: RES, 10.0 k, 1%, 0.063 W, AEC-Q200 Grade 0, 0402; Manufacturer: Vishay-Dale; Res_ohm: 10k; Value_Code: 10k0; Power_W: 63mW; Value2: 0.063W; VDC_V: 50V; TempCo: 100 ppm/C; EIA_Code: E96; SizeX_mm: 1; SizeY_mm: 0.5; SizeZ_mm: 0.6; AEC Qualified: Y; AEC Category: Q200; AEC Grade: 0
R17 R18 = CMP-0025703-4: RES, 10, 5%, 0.1 W, AEC-Q200 Grade 0, 0603; PartNumber: CRCW060310R0JNEA; Manufacturer: Vishay-Dale; Value: 10; Value_Code: 10R0; Power_W: 100mW; Value2: 0.1W; VDC_V: 75V; TempCo: 200 ppm/C; EIA_Code: E24; U/M: EA; SizeX_mm: 1.6; SizeY_mm: 0.8; SizeZ_mm: 1; SizeArea_mm2: 1.28; AEC Qualified: Y; AEC Category: Q200; AEC Grade: 0
R19 = CMP-0022268-4: RES, 2.00 k, 1%, 0.1 W, AEC-Q200 Grade 0, 0603; PartNumber: CRCW06032K00FKEA; Manufacturer: Vishay-Dale; Res_ohm: 2k; Value_Code: 2k00; Power_W: 100mW; Value2: 0.1W; VDC_V: 75V; TempCo: 100 ppm/C; EIA_Code: E96; U/M: EA; SizeX_mm: 1.6; SizeY_mm: 0.8; SizeZ_mm: 1; SizeArea_mm2: 1.28; AEC Qualified: Y; AEC Category: Q200; AEC Grade: 0
R21 R30 R32 = CMP-0025829-4: RES, 56, 5%, 0.1 W, AEC-Q200 Grade 0, 0603; PartNumber: CRCW060356R0JNEA; Manufacturer: Vishay-Dale; Value: 56; Value_Code: 56R0; Power_W: 100mW; Value2: 0.1W; VDC_V: 75V; TempCo: 200 ppm/C; EIA_Code: E24; U/M: EA; SizeX_mm: 1.6; SizeY_mm: 0.8; SizeZ_mm: 1; SizeArea_mm2: 1.28; AEC Qualified: Y; AEC Category: Q200; AEC Grade: 0
R23 = CMP-0026021-3: RES, 150 k, 1%, 0.063 W, AEC-Q200 Grade 0, 0402; Manufacturer: Vishay-Dale; Value: 150k; Power_W: 63mW; Value2: 0.063W; VDC_V: 50V; TempCo: 100 ppm/C; EIA_Code: E96; SizeX_mm: 1; SizeY_mm: 0.5; SizeZ_mm: 0.6; AEC Qualified: Y; AEC Category: Q200; AEC Grade: 0
R25 = CMP-0026721-1: RES, 100 k, 1%, 0.0625 W, 0402; Manufacturer: Yageo America; Value: 100k; Power_W: 62.5mW; VDC_V: 50V; TempCo: 100 ppm/C; EIA_Code: E96; SizeX_mm: 1; SizeY_mm: 0.5; SizeZ_mm: 0.6; AEC Qualified: N; AEC Category: Q200; U/M: EA
R27 = CMP-0025958-3: RES, 10.0 k, 1%, 0.063 W, AEC-Q200 Grade 0, 0402; PartNumber: CRCW040210K0FKED; Manufacturer: Vishay-Dale; Value: 10.0k; Res_ohm: 10k; Value_Code: 10k0; Power_W: 63mW; Value2: 0.063W; VDC_V: 50V; TempCo: 100 ppm/C; EIA_Code: E96; SizeX_mm: 1; SizeY_mm: 0.5; SizeZ_mm: 0.6; AEC Qualified: Y; AEC Category: Q200; AEC Grade: 0
R28 = CMP-0078584-1: RES, 33.0 k, 1%, 0.063 W, 0402; Manufacturer: Yageo America; Value: 33.0k; Res_ohm: 33k; Value_Code: 33k0; Power_W: 63mW; Value2: 0.063W; TempCo: 100 ppm/C; SizeX_mm: 1; SizeY_mm: 0.5; SizeZ_mm: 0.6; AEC Qualified: N; AEC Category: Q200
R29 = CMP-0026071-3: RES, 1.00 k, 1%, 0.063 W, AEC-Q200 Grade 0, 0402; Manufacturer: Vishay-Dale; Value: 1.00k; Res_ohm: 1k; Value_Code: 1k00; Power_W: 63mW; Value2: 0.063W; VDC_V: 50V; TempCo: 100 ppm/C; EIA_Code: E96; SizeX_mm: 1; SizeY_mm: 0.5; SizeZ_mm: 0.6; AEC Qualified: Y; AEC Category: Q200; AEC Grade: 0
R33 = CMP-0026893-2: RES, 2.0 M, 5%, 0.063 W, AEC-Q200 Grade 0, 0402; Manufacturer: Vishay-Dale; Value: 2.0Meg; Res_ohm: 2M; Value_Code: 2M00; Power_W: 63mW; Value2: 0.063W; VDC_V: 50V; TempCo: 200 ppm/C; EIA_Code: E24; SizeX_mm: 1; SizeY_mm: 0.5; SizeZ_mm: 0.6; AEC Qualified: Y; AEC Category: Q200; AEC Grade: 0
R34 R35 = CMP-0018679-3: RES, 3.9, 5%, 0.25 W, AEC-Q200 Grade 0, 1206; PartNumber: CRCW12063R90JNEA; Manufacturer: Vishay-Dale; Value_Code: 3R90; Power_W: 250mW; Value2: 0.25W; VDC_V: 200V; TempCo: 200 ppm/C; EIA_Code: E24; U/M: EA; SizeX_mm: 3.2; SizeY_mm: 1.6; SizeZ_mm: 1.35; SizeArea_mm2: 5.12; AEC Qualified: Y; AEC Category: Q200; AEC Grade: 0
R44 = CMP-0022735-5: RES, 100 k, 1%, 0.1 W, 0603; Manufacturer: Yageo; Value: 100k; Power_W: 100mW; Value2: 0.1W; VDC_V: 75V; TempCo: 100 ppm/C; EIA_Code: E96; SizeX_mm: 1.6; SizeY_mm: 0.8; SizeZ_mm: 1; SizeArea_mm2: 1.28; AEC Qualified: N; AEC Category: Q200; SizeAreaWB_mm2: 4.68
R45 = CMP-0026822-3: RES, 0, 5%, 0.063 W, AEC-Q200 Grade 0, 0402; Manufacturer: Vishay-Dale; Value_Code: 0000; Power_W: 63mW; Value2: 0.063W; VDC_V: 50V; TempCo: 200 ppm/C; EIA_Code: E24; SizeX_mm: 1; SizeY_mm: 0.5; SizeZ_mm: 0.6; AEC Qualified: Y; AEC Category: Q200
R46 R50 = CMP-0017299-3: RES, 10.0, 1%, 0.25 W, AEC-Q200 Grade 0, 1206; Manufacturer: Panasonic; Value: 10.0; Res_ohm: 10; Value_Code: 10R0; Power_W: 250mW; Value2: 0.25W; VDC_V: 200V; TempCo: 100 ppm/C; EIA_Code: E96; SizeX_mm: 3.2; SizeY_mm: 1.6; SizeZ_mm: 1.35; SizeArea_mm2: 5.12; AEC Qualified: Y; AEC Category: Q200; AEC Grade: 0; SizeAreaWB_mm2: 10.92
R47 = CMP-0025743-4: RES, 1.0, 5%, 0.1 W, AEC-Q200 Grade 0, 0603; Manufacturer: Vishay-Dale; Value: 1.0; Res_ohm: 1; Value_Code: 1R00; Power_W: 100mW; Value2: 0.1W; VDC_V: 75V; TempCo: 200 ppm/C; EIA_Code: E24; AEC Category: Q200; AEC Qualified: Y; AEC Grade: 0; SizeX_mm: 1.6; SizeY_mm: 0.8; SizeArea_mm2: 1.28
R48 = CMP-0025958-3: RES, 10.0 k, 1%, 0.063 W, AEC-Q200 Grade 0, 0402; Manufacturer: Vishay-Dale; Value: 10.0k; Res_ohm: 10k; Value_Code: 10k0; Power_W: 63mW; Value2: 0.063W; VDC_V: 50V; TempCo: 100 ppm/C; EIA_Code: E96; SizeX_mm: 1; SizeY_mm: 0.5; SizeZ_mm: 0.6; AEC Qualified: Y; AEC Category: Q200; AEC Grade: 0
R49 = CMP-0021042-3: RES, 20.0 k, 1%, 0.125 W, AEC-Q200 Grade 0, 0805; Manufacturer: Vishay-Dale; Value: 20.0k; Res_ohm: 20k; Value_Code: 20k0; Power_W: 125mW; Value2: 0.125W; VDC_V: 150V; TempCo: 100 ppm/C; EIA_Code: E96; SizeX_mm: 2; SizeY_mm: 1.25; SizeZ_mm: 1.45; SizeArea_mm2: 2.5; AEC Qualified: Y; AEC Category: Q200; AEC Grade: 0
R51 = CMP-0092287-1: 100 ±5% 0.063W, 1/16W Chip Resistor 0402 (1005 Metric) Moisture Resistant Thick Film; Manufacturer: Yageo; Power_W: 63mW; VDC_V: 50V; TempCo: 100ppm/°C; AEC Qualified: No; SizeZ_mm: 0.4mm
RAC_A RAC_B = CMP-0018570-2: RES, 0.01, 1%, 1 W, 1206; Manufacturer: Vishay-Dale; Value: 0.01; Res_ohm: 10m; Value_Code: R010; Power_W: 1W; TempCo: 75 ppm/C; EIA_Code: E96; SizeX_mm: 3.2; SizeY_mm: 1.6; SizeZ_mm: 1.35; SizeArea_mm2: 5.12; AEC Category: Q200; U/M: EA
RSR = CMP-0016512-2: RES, 0.005, 1%, 1.5 W, 2010; Manufacturer: Stackpole Electronics Inc; Value: 0.005; Res_ohm: 5m; Value_Code: 5L000; Power_W: 1.5W; TempCo: 50 ppm/C; EIA_Code: E96; AEC Category: Q200; U/M: EA; SizeX_mm: 5; SizeY_mm: 2.5; SizeZ_mm: 1.66; SizeArea_mm2: 12.5
TP1 TP22-TP24 TP29 TP31 TP32 = CMP-0055147-2: Test Point, Multipurpose, Red, TH; Manufacturer: Keystone Electronics; CNHeader: FALSE; Green_Lifecycle: Active; Green_REACh: Passed; CT: TRUE; ContactFinish: Silver
TP15-TP17 = CMP-0055152-2: Test Point, Miniature, SMT; Manufacturer: Keystone Electronics; CNHeader: FALSE; Green_Lifecycle: Active; Green_REACh: Passed; CT: TRUE
TP18-TP21 TP30 TP41 = CMP-0055148-2: Test Point, Multipurpose, Black, TH; Manufacturer: Keystone Electronics; CNHeader: FALSE; Green_Lifecycle: Active; Green_REACh: Passed; CT: TRUE; ContactFinish: Silver
U1 = CMP-0121663-1: 40-V, SMBus, 2- to 5-Cell, Narrow VDC Quasi Dual Phase Buck-Boost Battery Charge Controller With System Power Monitor and Processor Hot Monitor; Manufacturer: Texas Instruments; SizeZ_mm: 0.8mm; Min Supply Voltage: 3.5V; Standoff Height: 0mm; Max Supply Voltage: 40V; Number Of Cells: 5; Number Of Outputs: 2; AEC Qualified: No; AEC Grade: NA
U2 = CMP-0035936-3: 60V, 5uA IQ Low-Dropout 100mA Linear Regulator with Enable and Power Good, DGN0008C (VSSOP-8); Manufacturer: Texas Instruments; Alternate PartNumber: TPS7A1633DGNT; Alternate Manufacturer: None; CompType: IC; SizeArea_mm2: 14.7; SizeAreaWB_mm2: 23.6; SizeY_mm: 3.0; SizeZ_mm: 1.1; SizeX_mm: 4.9; AEC Category: Q200; AEC Qualified: N; Vin(Max)(V): 60; SubFamily: Single Channel LDO; Iout(Max)(A): 0.1; Power Good: TRUE; Vin(Min)(V): 3; Eco-Plan: Green (RoHS & no Sb/Br); Fixed Output Options(V): 3.3; Iq(Typ)(mA): 0.004; Rating: Catalog; Accuracy(%): 2
Z1 = CMP-0084947-1: Diode, TVS, Uni, 10 V, 17 Vc, 400 W, 23.5 A, SMA; Manufacturer: Littelfuse; Value1: 17V; RJA_CperW: 120; SizeAreaWB_mm2: 37.3428; SizeZ_mm: 2.87; SizeX_mm: 5.59; SizeY_mm: 2.92; SizeArea_mm2: 16.3228; AEC Qualified: N; AEC Category: Q101; Ipp: 23.5A; Ppk: 400W; Vbr_Max: 12.3V; Vbr_Min: 11.1V

## Sheet PMP22405A_Hardware.SchDoc: EVM hardware
size 431 x 279 mm; Date: Not shown in title block; ApprovedBy: Not shown in title block; CheckedBy: Not shown in title block; Author: Not shown in title block; CompanyName: Not shown in title block; Engineer: Not shown in title block; Organization: Not shown in title block; Address1: Not shown in title block; Address2: Not shown in title block; Address3: Not shown in title block; Address4: Not shown in title block; DocumentNumber: 2; Revision: Use project parameter SCH_Rev; SheetNumber: 2; SheetTotal: 2; PageSetup: Record=PageOptions¦CenterHorizontal=True¦CenterVertical=True¦PrintScale=1.00¦XCorrection=1.00¦YCorrection=1.00¦PrintKind=0¦BorderSize=5000000¦LeftOffset=0¦BottomOffset=0¦Orientation=2¦PaperLength=1000¦PaperWidth=1000¦Scale=100¦PaperSource=15¦PrintQuality=600¦MediaType=1¦DitherType=10¦PaperKind=Letter¦PrintScaleMode=1
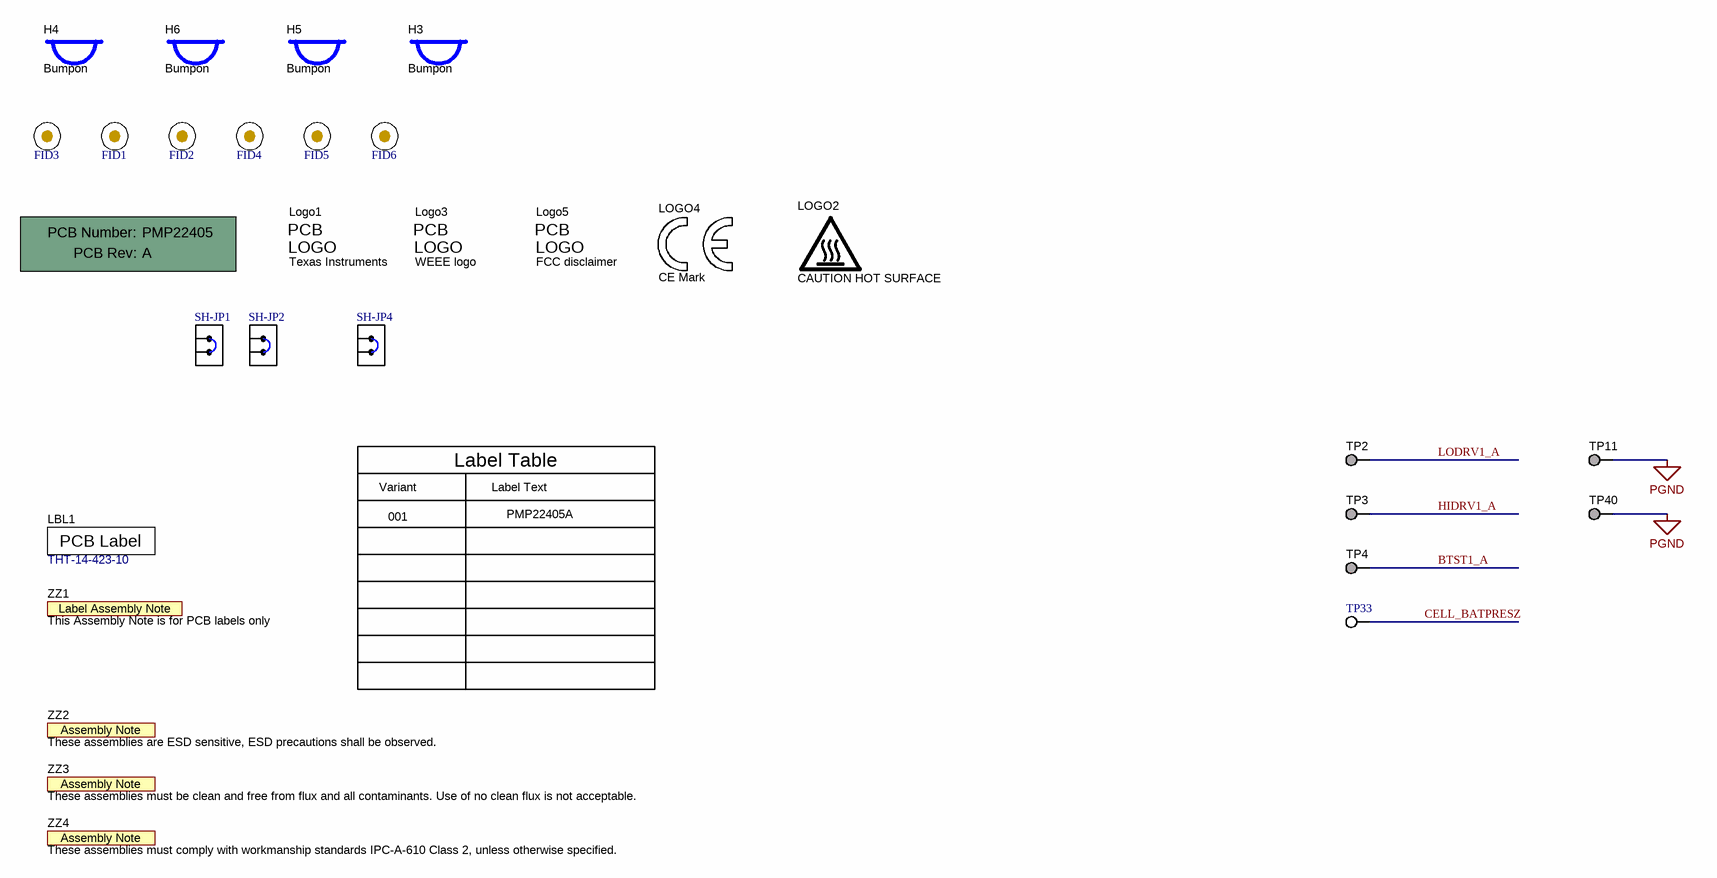
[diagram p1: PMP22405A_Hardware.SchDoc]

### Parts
!PCB1  Printed Circuit Board  (value not drawn)  (mechanical)
FID1  Fiducial  [Fiducial10-20]  (value not drawn)  (no BOM)
FID2  Fiducial  [Fiducial10-20]  (value not drawn)  (no BOM)
FID3  Fiducial  [Fiducial10-20]  (value not drawn)  (no BOM)
FID4  Fiducial  [Fiducial10-20]  (value not drawn)  (no BOM)
FID5  Fiducial  [Fiducial10-20]  (value not drawn)  (no BOM)
FID6  Fiducial  [Fiducial10-20]  (value not drawn)  (no BOM)
H3  Bumpon  [Bumpon_SJ5003Transparent]
H4  Bumpon  [Bumpon_SJ5003Transparent]
H5  Bumpon  [Bumpon_SJ5003Transparent]
H6  Bumpon  [Bumpon_SJ5003Transparent]
LBL1  THT-14-423-10  [Label_650x200]
Logo1  Texas Instruments  [TI_Stacked_Overlay_Small]  (no BOM)
LOGO2  CAUTION HOT SURFACE  [IEC_HotSurface_Small]  (no BOM)
Logo3  WEEE logo  [WEEE_Minimum]  (no BOM)
LOGO4  CE Mark  [CE_Mark_5mm]  (no BOM)
Logo5  FCC disclaimer  [FCC_disclaimer]  (no BOM)
SH-JP1  SNT-100-BK-G  [SNT-100-BK-G]  (value not drawn)
SH-JP2  SNT-100-BK-G  [SNT-100-BK-G]  (value not drawn)
SH-JP4  SNT-100-BK-G  [SNT-100-BK-G]  (value not drawn)
TP2  RCU-0C  [TE_RCU]  (value not drawn)
TP3  RCU-0C  [TE_RCU]  (value not drawn)
TP4  RCU-0C  [TE_RCU]  (value not drawn)
TP11  RCU-0C  [TE_RCU]  (value not drawn)
TP33  5015  [Testpoint_Keystone_Miniature]  (value not drawn)
TP40  RCU-0C  [TE_RCU]  (value not drawn)
ZZ1  This Assembly Note is for PCB labels only  [AssemblyNoteLabel]  (no BOM)
ZZ2  These assemblies are ESD sensitive, ESD precautions shall be observed.  [AssemblyNote]  (no BOM)
ZZ3  These assemblies must be clean and free from flux and all contaminants. Use of no clean flux is not acceptable.  [AssemblyNote]  (no BOM)
ZZ4  These assemblies must comply with workmanship standards IPC-A-610 Class 2, unless otherwise specified.  [AssemblyNote]  (no BOM)

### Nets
PGND: TP11.1 TP40.1
BTST1_A: TP4.1
CELL_BATPRESZ: TP33.1
HIDRV1_A: TP3.1
LODRV1_A: TP2.1

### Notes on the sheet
- Variant
- 001
- Label Table
- PMP22405A
- Label Text

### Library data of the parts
!PCB1 = CMP-0003618-2: Manufacturer: Any; PartNumber: PMP22405; SymbolCreator: a0412235
FID1-FID6 = CMP-0077181-1: Fiducial mark.  There is nothing to buy or mount.; SymbolCreator: codlsc
H3-H6 = CMP-0003620-1: Bumpon, Hemisphere, 0.44 X 0.20, Clear; Manufacturer: 3M; PartNumber: SJ-5303 (CLEAR); SymbolCreator: a0412235
LBL1 = CMP-0003625-1: Thermal Transfer Printable Labels, 0.650" W x 0.200" H - 10,000 per roll; Manufacturer: Brady; Note: Size: 0.65" x 0.20 "
Logo1 = CMP-0074838-1: Texas Instrument Corporate Signature; SymbolCreator: a0412235; Library Reference: Logo; Lib Reference: TI_Logo
LOGO2 = CMP-0074837-2: IEC 61010-1 Hot Surface Warning; Manufacturer: Texas Instruments; SymbolCreator: a0412235; CompType: IC; AEC Category: Q200
Logo3 = CMP-0074769-3: Manufacturer: Texas Instruments; AEC Category: Q200; CompType: IC
LOGO4 = CMP-0074844-1: SymbolCreator: a0412235
Logo5 = CMP-0074847-1: FCC_disclaimer; SymbolCreator: codlsc; Library Reference: Logo
SH-JP1 SH-JP2 SH-JP4 = CMP-0003623-3: Shunt, 100mil, Gold plated, Black; Manufacturer: Samtec; Alternate Manufacturer: 3M; Alternate PartNumber: 969102-0000-DA; Value: 1x2; Note: You can "mate" this to a header by matching the designator.  i.e. use SH-J3 for header J3
TP2-TP4 TP11 TP40 = CMP-0067620-1: PC Test Point, SMT; Manufacturer: TE Connectivity
TP33 = CMP-0055152-2: Test Point, Miniature, SMT; Manufacturer: Keystone Electronics; CT: TRUE; Green_Lifecycle: Active; Green_REACh: Passed; CNHeader: FALSE
ZZ1 = CMP-0003616-3: SymbolCreator: a0412235
ZZ2 = CMP-0077236-1: SymbolCreator: codlsc
ZZ3 = CMP-0077237-1: SymbolCreator: codlsc
ZZ4 = CMP-0077238-1: SymbolCreator: codlsc

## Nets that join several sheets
PGND: PMP22405A (83 pins), PMP22405A_Hardware (TP11.1 TP40.1)
BTST1_A: PMP22405A (C20.1 D2.1 U1.3), PMP22405A_Hardware (TP4.1)
CELL_BATPRESZ: PMP22405A (8 pins), PMP22405A_Hardware (TP33.1)
HIDRV1_A: PMP22405A (Q1_A.1 U1.4), PMP22405A_Hardware (TP3.1)
LODRV1_A: PMP22405A (Q2_A.4 U1.1), PMP22405A_Hardware (TP2.1)

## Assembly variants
001: not fitted C3 C4 C13 C33 C34 C47 C49 C50 C51 C57 C60 C62 C63 C64 C65 C66 C67 C68 C69 C70 D2 D3 D4 D5 D6 Q6 Q9 Q10 R21 R30 R32 R44 R46 R48 R49 R51 SH-JP2 Z1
